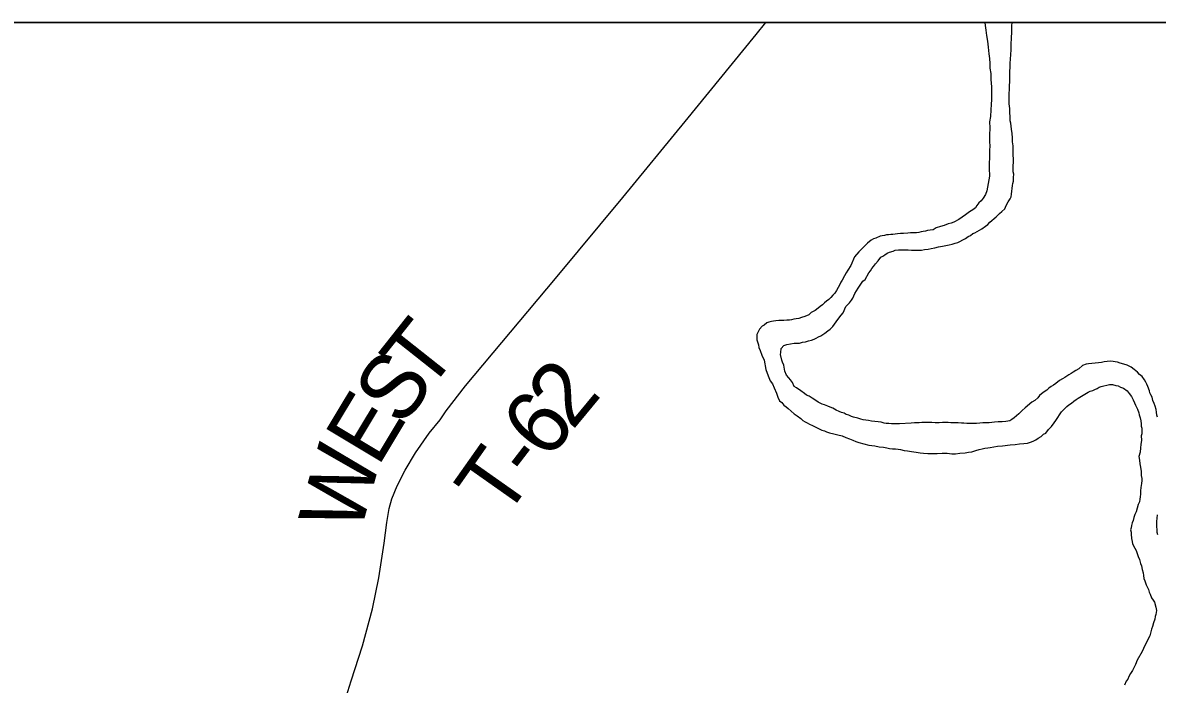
# Model space of a CAD drawing. Extents: x 0 to 34, y 0 to 22.
# Drawn here: x 4.688 to 5.693, y 20.314 to 20.9 of the extents above; entities that cross this region are included whole.
import ezdxf

# ---------------------------------------------------------------- set-up
doc = ezdxf.new("R2010")
doc.units = 0
for name, color, linetype in [('GM_X_Corporation', 7, 'Continuous'), ('GM_X_Major_River', 7, 'Continuous'), ('GM_X_Township_Road', 7, 'Continuous'), ('GM_X_Township_Road_Text', 7, 'Continuous'), ('SH_Data', 7, 'Continuous')]:
    doc.layers.add(name, color=color, linetype=linetype)

msp = doc.modelspace()

# ---------------------------------------------------------------- linework, layer by layer
at = {"layer": 'GM_X_Corporation'}
for points in [[(7.8853, 20.9), (2.1, 20.9)], [(7.8853, 20.9), (2.6713, 20.9)]]:
    msp.add_lwpolyline(points, dxfattribs=at)
at = {"layer": 'GM_X_Major_River'}
for points in [[(5.4677, 20.6987), (5.47, 20.6988), (5.4723, 20.6988), (5.4754, 20.6984), (5.478, 20.6985), (5.4811, 20.6985), (5.4841, 20.6985), (5.4868, 20.6989), (5.4902, 20.6994), (5.4928, 20.6998), (5.4959, 20.7006), (5.4993, 20.7014), (5.5027, 20.7018), (5.5057, 20.7026), (5.5088, 20.703), (5.5114, 20.7038), (5.5141, 20.7046), (5.5163, 20.7053), (5.5182, 20.7061), (5.5209, 20.7077), (5.5231, 20.7088), (5.5254, 20.7104), (5.5277, 20.7115), (5.5296, 20.7131), (5.5315, 20.7139), (5.5375, 20.7174), (5.5409, 20.7197), (5.5428, 20.7212), (5.5447, 20.7231), (5.5466, 20.7247), (5.5484, 20.7266), (5.5503, 20.7278), (5.5533, 20.7308), (5.5552, 20.7328), (5.5579, 20.7351), (5.5593, 20.7381), (5.5608, 20.7412), (5.5627, 20.7439), (5.5635, 20.7458), (5.5638, 20.7481), (5.5642, 20.7507), (5.5645, 20.753), (5.5649, 20.7557), (5.5652, 20.7576), (5.5656, 20.7595), (5.5656, 20.7629), (5.5659, 20.7656), (5.5655, 20.7679), (5.5655, 20.7709), (5.5655, 20.7732), (5.5658, 20.7763), (5.5658, 20.7793), (5.5654, 20.7827), (5.5653, 20.7854), (5.5653, 20.788), (5.5653, 20.7907), (5.5649, 20.7945), (5.5648, 20.7979), (5.5644, 20.8017), (5.564, 20.8055), (5.5636, 20.8082), (5.5632, 20.8109), (5.5628, 20.8131), (5.5623, 20.8238), (5.5619, 20.828), (5.5618, 20.8318), (5.5618, 20.8352), (5.5618, 20.8379), (5.5621, 20.8401), (5.5621, 20.8436), (5.5624, 20.8481), (5.5624, 20.8519), (5.5623, 20.8569), (5.5627, 20.8603), (5.5626, 20.8641), (5.563, 20.8676), (5.5633, 20.8717), (5.5637, 20.8759), (5.5636, 20.8809), (5.5639, 20.8862), (5.5643, 20.8919), (5.5642, 20.8972), (5.5644, 20.9)], [(5.5404, 20.9), (5.5406, 20.8974), (5.5411, 20.8932), (5.5419, 20.8886), (5.5427, 20.8837), (5.5431, 20.8784), (5.5439, 20.8723), (5.5444, 20.8681), (5.5448, 20.8639), (5.5448, 20.8598), (5.5456, 20.8548), (5.5457, 20.8495), (5.5461, 20.843), (5.5462, 20.8369), (5.5462, 20.832), (5.5459, 20.8274), (5.5456, 20.8228), (5.5453, 20.8168), (5.5445, 20.8122), (5.5446, 20.8069), (5.5443, 20.8004), (5.5443, 20.7947), (5.5448, 20.7905), (5.5444, 20.7871), (5.5444, 20.784), (5.5445, 20.7817), (5.5445, 20.7795), (5.5441, 20.776), (5.5442, 20.7711), (5.5443, 20.7639), (5.5421, 20.7509), (5.541, 20.7478), (5.5388, 20.7444), (5.5369, 20.7421), (5.535, 20.7402), (5.5331, 20.7379), (5.532, 20.7359), (5.5297, 20.734), (5.5267, 20.7325), (5.5233, 20.7298), (5.5203, 20.7275), (5.5173, 20.7255), (5.5127, 20.7232), (5.5105, 20.7224), (5.5078, 20.7216), (5.5044, 20.7204), (5.501, 20.7193), (5.4972, 20.7181), (5.4946, 20.7165), (5.4919, 20.7161), (5.4896, 20.7157), (5.4877, 20.7153), (5.4858, 20.7149), (5.4839, 20.7145), (5.4817, 20.7141)], [(5.4817, 20.7141), (5.4798, 20.7137), (5.4771, 20.7137), (5.4744, 20.7137), (5.4722, 20.7136), (5.4684, 20.7132), (5.4657, 20.7132), (5.463, 20.7128), (5.4589, 20.7124), (5.457, 20.7123), (5.4551, 20.7119), (5.4532, 20.7119), (5.4513, 20.7115), (5.4494, 20.7111), (5.4475, 20.7107), (5.4437, 20.7091), (5.4418, 20.7084), (5.4395, 20.7072), (5.4365, 20.7045), (5.4343, 20.7026), (5.4286, 20.6968), (5.4249, 20.6926), (5.4215, 20.6849), (5.4189, 20.6807), (5.4174, 20.6784), (5.4159, 20.6758), (5.414, 20.6719), (5.4129, 20.67), (5.4118, 20.6681), (5.4103, 20.6654), (5.4088, 20.6627), (5.4073, 20.6604), (5.4058, 20.6585), (5.4039, 20.6566), (5.402, 20.6547), (5.4002, 20.6531), (5.3983, 20.6516), (5.3964, 20.6501), (5.3945, 20.6485), (5.3926, 20.647), (5.39, 20.645), (5.3866, 20.6431), (5.3843, 20.6412), (5.3809, 20.6396), (5.3779, 20.6388), (5.3756, 20.638), (5.3733, 20.6376), (5.3711, 20.6372), (5.3692, 20.6368), (5.3673, 20.6364), (5.365, 20.6364), (5.3623, 20.636), (5.36, 20.636), (5.3578, 20.636), (5.3551, 20.6359), (5.3532, 20.6355), (5.3513, 20.6351), (5.349, 20.6347), (5.3471, 20.6339), (5.3449, 20.632), (5.343, 20.6312), (5.3407, 20.6285), (5.3392, 20.6255), (5.3385, 20.6236), (5.3385, 20.619), (5.3389, 20.6171), (5.3397, 20.6145), (5.3401, 20.6122), (5.3413, 20.6095), (5.3429, 20.6054), (5.3448, 20.6008), (5.3464, 20.5928), (5.3484, 20.5871), (5.3503, 20.5826), (5.3522, 20.58), (5.3538, 20.5765), (5.3557, 20.5716), (5.3569, 20.5682), (5.3585, 20.5648), (5.3604, 20.5633), (5.3623, 20.561), (5.3642, 20.5595), (5.3661, 20.558), (5.3688, 20.5558), (5.3715, 20.5535), (5.3742, 20.5516), (5.3773, 20.5494), (5.3792, 20.5475), (5.3811, 20.5464), (5.383, 20.5453), (5.3849, 20.5441), (5.3876, 20.543), (5.3906, 20.5415), (5.3937, 20.5401), (5.396, 20.5389), (5.3983, 20.5382), (5.4002, 20.5375), (5.4028, 20.5367), (5.4067, 20.5356), (5.4101, 20.5349), (5.4139, 20.5338)], [(5.4845, 20.5456), (5.4822, 20.5455), (5.4799, 20.5455), (5.478, 20.5455), (5.475, 20.5451), (5.4647, 20.5446), (5.4617, 20.5446), (5.4594, 20.5445), (5.4575, 20.5445), (5.4552, 20.5449), (5.4529, 20.5449), (5.451, 20.5452), (5.4484, 20.5459), (5.4457, 20.5463), (5.443, 20.5467), (5.44, 20.547), (5.4373, 20.5474), (5.435, 20.5477), (5.4324, 20.5481), (5.4305, 20.5488), (5.4278, 20.5495), (5.424, 20.5503), (5.4221, 20.551), (5.4198, 20.5521), (5.4175, 20.5529), (5.4156, 20.554), (5.4133, 20.5547), (5.4114, 20.5555), (5.4087, 20.5566), (5.4057, 20.5584), (5.4034, 20.5592), (5.4011, 20.5603), (5.3984, 20.5614), (5.3961, 20.5621), (5.3927, 20.5636), (5.3896, 20.5659), (5.3873, 20.5674), (5.3847, 20.5689), (5.3824, 20.57), (5.3805, 20.5715), (5.3774, 20.5737), (5.3736, 20.5764), (5.3713, 20.5775), (5.3701, 20.5813), (5.3682, 20.5835), (5.3666, 20.5854), (5.3647, 20.5877), (5.3632, 20.5911), (5.3623, 20.5964), (5.3612, 20.5991), (5.3604, 20.601), (5.3592, 20.6059), (5.3596, 20.6078), (5.3599, 20.6112), (5.3622, 20.6139), (5.3648, 20.6147), (5.3713, 20.6159), (5.3743, 20.616), (5.3762, 20.616), (5.3789, 20.6168), (5.3815, 20.6172), (5.3842, 20.618), (5.3868, 20.6187), (5.3891, 20.6195), (5.391, 20.6203), (5.3929, 20.6215), (5.3951, 20.6226), (5.3985, 20.625), (5.4012, 20.6269), (5.4034, 20.6284), (5.4057, 20.6307), (5.4072, 20.6327), (5.4102, 20.6369), (5.4132, 20.6407), (5.4147, 20.643), (5.4173, 20.6484), (5.4203, 20.6518), (5.4222, 20.6541), (5.4233, 20.656), (5.4252, 20.6599), (5.4267, 20.6625), (5.4282, 20.6648), (5.4304, 20.6683), (5.4323, 20.671), (5.4342, 20.6725), (5.4375, 20.6783), (5.439, 20.6802), (5.4402, 20.6821), (5.4417, 20.684), (5.4435, 20.6863), (5.4458, 20.689), (5.4481, 20.6921), (5.4499, 20.6932), (5.4518, 20.6944), (5.4537, 20.6956), (5.456, 20.6967), (5.459, 20.6975), (5.4609, 20.6983), (5.4639, 20.6987), (5.4658, 20.6987), (5.4677, 20.6987)], [(5.6931, 20.5504), (5.6927, 20.5523), (5.6923, 20.555), (5.6919, 20.5572), (5.6911, 20.5603), (5.6903, 20.5626), (5.6892, 20.5652), (5.6884, 20.5682), (5.6872, 20.5701), (5.6864, 20.572), (5.686, 20.5739), (5.6845, 20.5777), (5.6837, 20.5796), (5.6829, 20.5815), (5.6818, 20.5834), (5.6795, 20.5864), (5.6772, 20.5883), (5.6756, 20.5902), (5.6726, 20.5928), (5.6699, 20.5947), (5.6664, 20.5966), (5.6634, 20.5973), (5.66, 20.5984), (5.6577, 20.5991), (5.6558, 20.5995), (5.6539, 20.5998), (5.6512, 20.6002), (5.6485, 20.5998), (5.6459, 20.5994), (5.6436, 20.599), (5.6409, 20.5986), (5.6379, 20.5982), (5.6349, 20.5981), (5.6322, 20.5977), (5.6299, 20.5973), (5.6269, 20.5961), (5.6235, 20.5934), (5.6209, 20.5919), (5.6186, 20.5903), (5.6167, 20.5892), (5.6148, 20.588), (5.6129, 20.5869), (5.611, 20.5857), (5.6092, 20.5845), (5.6065, 20.583), (5.6031, 20.5803), (5.6012, 20.5787), (5.599, 20.5776), (5.5971, 20.576), (5.5952, 20.5745), (5.5918, 20.5722), (5.5888, 20.5695), (5.5873, 20.5676), (5.5846, 20.5653), (5.582, 20.5637), (5.576, 20.5587), (5.5733, 20.5564), (5.5703, 20.5533), (5.5662, 20.5498), (5.5643, 20.5483), (5.5624, 20.5471), (5.559, 20.5467), (5.5556, 20.5463), (5.5521, 20.5463), (5.5487, 20.5459), (5.5442, 20.5454), (5.5411, 20.5454), (5.5385, 20.5454), (5.5358, 20.545), (5.5328, 20.5449), (5.5297, 20.5449), (5.5271, 20.5449), (5.5244, 20.5448), (5.5217, 20.5452), (5.5195, 20.5452), (5.5168, 20.5455), (5.5141, 20.5455), (5.5103, 20.5455), (5.5077, 20.5458), (5.5054, 20.5458), (5.5027, 20.5458), (5.4997, 20.5453), (5.4963, 20.5453), (5.4932, 20.5457), (5.4902, 20.5456), (5.4871, 20.5456), (5.4845, 20.5456)], [(5.4139, 20.5338), (5.4173, 20.5323), (5.4204, 20.5312), (5.4234, 20.5301), (5.4261, 20.529), (5.4288, 20.5279), (5.4375, 20.5257), (5.4429, 20.525), (5.4467, 20.5242), (5.4505, 20.5239), (5.4535, 20.5232), (5.4558, 20.5228), (5.4585, 20.5225), (5.4611, 20.5225), (5.4634, 20.5221), (5.4657, 20.5218), (5.4688, 20.521), (5.4718, 20.5207), (5.4752, 20.52), (5.4794, 20.5193), (5.4829, 20.5189), (5.4859, 20.5186), (5.4897, 20.5182), (5.4939, 20.5183), (5.4981, 20.5183), (5.5026, 20.5184), (5.5068, 20.5184), (5.511, 20.5181), (5.5144, 20.5181), (5.5182, 20.5185), (5.5228, 20.5189), (5.5258, 20.5194), (5.5288, 20.5198), (5.5322, 20.5209), (5.5353, 20.5217), (5.5379, 20.5225), (5.5402, 20.5229), (5.5429, 20.5233), (5.5451, 20.5237), (5.5482, 20.5242), (5.5516, 20.5246), (5.5558, 20.525), (5.5626, 20.5258), (5.5672, 20.5263), (5.571, 20.5267), (5.5748, 20.5271), (5.5782, 20.5275), (5.5808, 20.5283), (5.5831, 20.5291), (5.5854, 20.5303), (5.5876, 20.5318), (5.5903, 20.5333), (5.5922, 20.5353), (5.5944, 20.5364), (5.5967, 20.5395), (5.5993, 20.5422), (5.6016, 20.5453), (5.6031, 20.5476), (5.6049, 20.5502), (5.6064, 20.5525), (5.6083, 20.5552), (5.6109, 20.5579), (5.6128, 20.5598), (5.6147, 20.5614), (5.617, 20.5629), (5.6192, 20.5645), (5.6211, 20.566), (5.623, 20.5672), (5.626, 20.5691), (5.6287, 20.5707), (5.6317, 20.5726), (5.6336, 20.5734), (5.6359, 20.5742), (5.6378, 20.5749), (5.6397, 20.5757), (5.6415, 20.5769), (5.6434, 20.5777), (5.6457, 20.5781), (5.6484, 20.5789), (5.6506, 20.5793), (5.6533, 20.5793), (5.6564, 20.5786), (5.6583, 20.5782), (5.6605, 20.5771), (5.6632, 20.576), (5.6663, 20.5737), (5.6682, 20.5715), (5.6701, 20.5688), (5.6717, 20.5658), (5.6729, 20.5631), (5.6736, 20.5612), (5.6756, 20.5575), (5.6767, 20.5544), (5.6771, 20.5525), (5.6779, 20.5499), (5.6783, 20.5472), (5.6787, 20.5445), (5.6788, 20.5426), (5.6792, 20.5407), (5.6792, 20.5385), (5.6792, 20.5358)], [(5.6792, 20.5358), (5.6788, 20.5339), (5.6789, 20.5301), (5.6785, 20.5263), (5.6782, 20.5232), (5.6778, 20.5194), (5.6767, 20.5156), (5.6772, 20.5122), (5.6776, 20.5091), (5.678, 20.5061), (5.6788, 20.5023), (5.6788, 20.4989), (5.6792, 20.4962), (5.6792, 20.4943), (5.6789, 20.4917), (5.6785, 20.4882), (5.6782, 20.4852), (5.6782, 20.4821), (5.6779, 20.4798), (5.6775, 20.4779), (5.6772, 20.4753), (5.676, 20.473), (5.6753, 20.4699), (5.6742, 20.4665), (5.6731, 20.4642), (5.6723, 20.4615), (5.6716, 20.4589), (5.6709, 20.4569), (5.6701, 20.4546), (5.6698, 20.4524), (5.6694, 20.4505), (5.6698, 20.4486), (5.6698, 20.4467), (5.6703, 20.4429), (5.6707, 20.4402), (5.6711, 20.4383), (5.673, 20.4345), (5.6742, 20.4322), (5.6753, 20.4296), (5.6761, 20.4269), (5.6773, 20.4243), (5.6781, 20.4209), (5.6789, 20.4186), (5.6796, 20.4156), (5.6804, 20.4125), (5.6808, 20.4102), (5.6812, 20.4076), (5.682, 20.4053), (5.6832, 20.4019), (5.684, 20.4), (5.6851, 20.3977), (5.6859, 20.3955), (5.6867, 20.3936), (5.6879, 20.3905), (5.6894, 20.3883), (5.6906, 20.3864), (5.6918, 20.3822), (5.6922, 20.3792), (5.6918, 20.3757), (5.6911, 20.3738), (5.6907, 20.3715), (5.6896, 20.3681), (5.6889, 20.365), (5.6878, 20.3627), (5.6863, 20.3566), (5.6848, 20.354), (5.6837, 20.3513), (5.6822, 20.3486), (5.6807, 20.3455), (5.6796, 20.3429), (5.6751, 20.3352), (5.6736, 20.3314), (5.6722, 20.3283), (5.671, 20.326), (5.6692, 20.3234), (5.6677, 20.3207), (5.6669, 20.3184), (5.6654, 20.3165), (5.6639, 20.313)], [(5.6934, 20.4461), (5.693, 20.4484), (5.693, 20.4511), (5.6926, 20.453), (5.6926, 20.4553), (5.6925, 20.4579), (5.6929, 20.461), (5.6932, 20.464)]]:
    msp.add_lwpolyline(points, dxfattribs=at)
at = {"layer": 'GM_X_Township_Road'}
msp.add_lwpolyline([(4.9717, 20.2933), (4.9791, 20.3167), (4.9893, 20.3479), (4.998, 20.3806), (5.0036, 20.408), (5.0083, 20.4388), (5.0107, 20.4572), (5.0127, 20.4694), (5.0152, 20.4782), (5.0198, 20.4897), (5.0269, 20.5035), (5.0361, 20.5189), (5.0481, 20.5363), (5.058, 20.5481), (5.0634, 20.556), (5.0805, 20.5781), (5.1602, 20.6734), (5.2196, 20.7452), (5.275, 20.8124), (5.3379, 20.8894), (5.3463, 20.9)], dxfattribs=at)
at = {"layer": 'SH_Data'}
msp.add_line((2.1, 20.9), (8.9, 20.9), dxfattribs=at)

# ---------------------------------------------------------------- texts
at = {"layer": 'GM_X_Township_Road_Text'}
for s, rotation, p in [('T', 51.624, (5.0464, 20.5709)), ('S', 53.2565, (5.0238, 20.5405)), ('2', 50.4266, (5.1749, 20.538)), ('E', 58.9782, (5.0027, 20.5054)), ('6', 50.9403, (5.1529, 20.5109)), ('W', 74.5125, (4.9867, 20.4456)), ('T', 54.8228, (5.1148, 20.4585)), ('-', 52.3667, (5.1389, 20.4927))]:
    msp.add_text(s, height=0.0568, rotation=rotation, dxfattribs=at).set_placement(p)

doc.saveas('drawing.dxf')
